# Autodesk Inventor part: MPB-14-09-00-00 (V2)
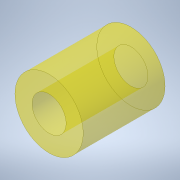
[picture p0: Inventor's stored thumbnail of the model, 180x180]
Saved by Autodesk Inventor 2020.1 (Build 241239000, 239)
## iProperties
Created: 2020-04
Part Number: MPB-14-09-00-00 (V2)
Material: PU Elastomer
Document SubType Name: Modeling
Designer: Safarabadi
Density: 0.93 g/cm^3
Appearance: Clear - Yellow
Author: Safarabadi
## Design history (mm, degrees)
derived "MPB-14-09-00-00.ipt"
feature "Solid1::MPB-14-09-00-00.ipt" dims "d0" = 10
tag "TaggingFeature1"
body "Solid1"
